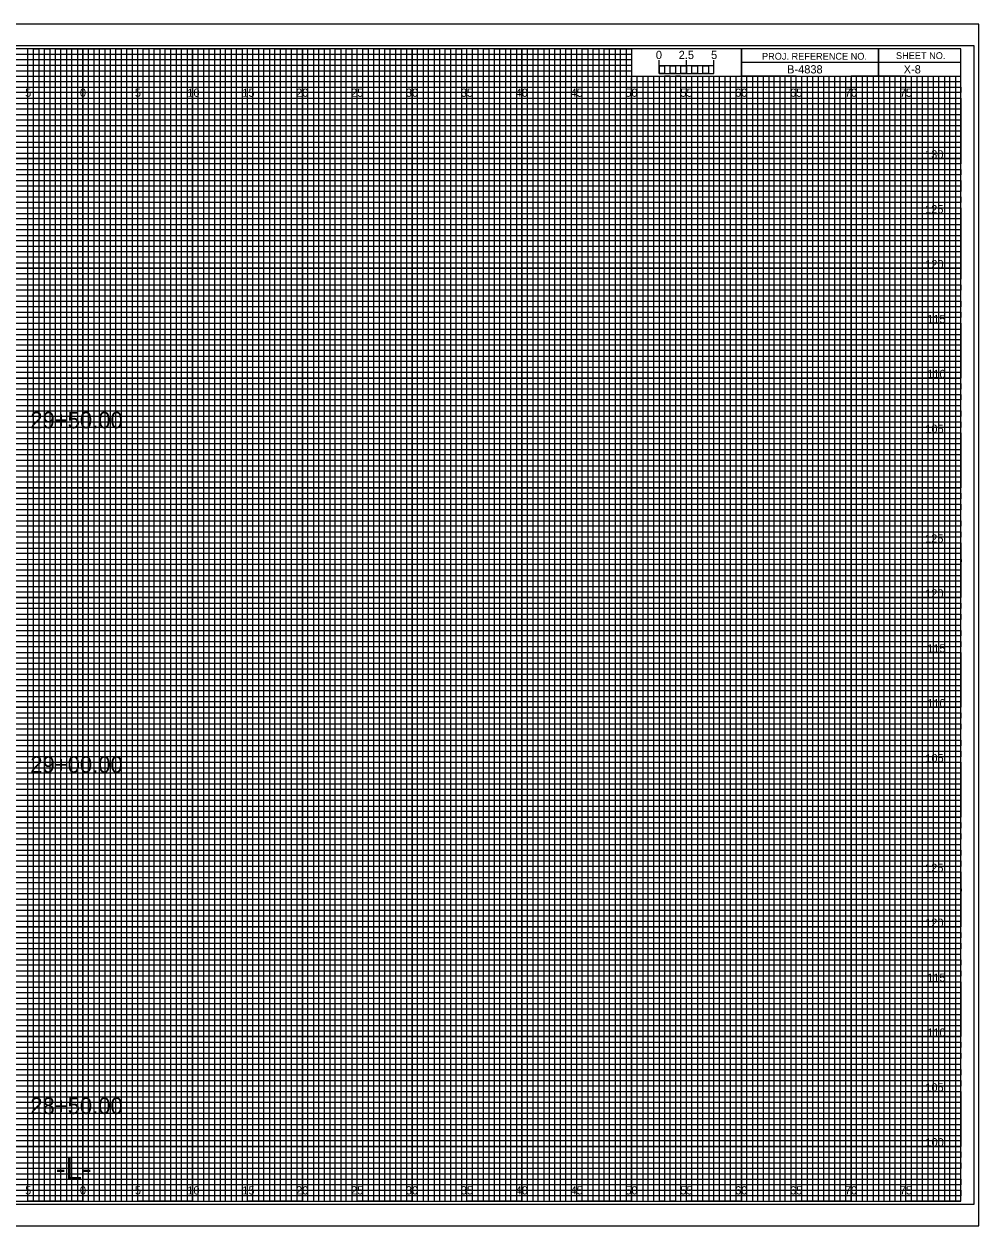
# Model space of a CAD drawing. Extents: x -7 to 182, y -2 to 1647.
# Drawn here: x 74.6 to 161.7, y 657.8 to 767.2 of the extents above; entities that cross this region are included whole.
import ezdxf

# ---------------------------------------------------------------- set-up
doc = ezdxf.new("R2010")
doc.units = 0
for name, color, linetype in [('Exist CMT Pavement', 7, 'Continuous'), ('Exist Cross Section Cell', 7, 'Continuous'), ('Exist XS Ground Line', 7, 'Continuous'), ('Prop CMT Pvmt Course 1', 7, 'Continuous'), ('Prop CMT Pvmt Course 2', 7, 'Continuous'), ('Prop CMT Pvmt Course 2 Wedge', 7, 'Continuous'), ('Prop CMT Pvmt Course 3', 7, 'Continuous'), ('Prop CMT Pvmt Surface', 7, 'Continuous'), ('Prop CMT Pvmt Surface Shoulder', 7, 'Continuous'), ('Prop CMT Pvmt Wedge Surface 1', 7, 'Continuous'), ('Prop CMT Pvmt Wedge Surface 2', 7, 'Continuous'), ('Prop CMT Pvmt Wedge Surface 3', 7, 'Continuous'), ('Prop CMT Shld Paved Course 1', 7, 'Continuous'), ('Prop CMT Shld Paved Course 2', 7, 'Continuous'), ('Prop CMT Shld Paved Course 3', 7, 'Continuous'), ('Prop CMT Slope Grass', 7, 'Continuous'), ('Prop CMT Subgrade Earthwork', 7, 'Continuous')]:
    doc.layers.add(name, color=color, linetype=linetype)

msp = doc.modelspace()

# ---------------------------------------------------------------- linework, layer by layer
at = {"layer": 'Exist XS Ground Line'}
for p, q in [((75, 765), (70, 765)), ((75, 660), (75, 765)), ((85, 765), (80, 765)), ((80, 765), (80, 660)), ((85, 660), (85, 765)), ((95, 765), (90, 765)), ((90, 765), (90, 660)), ((95, 660), (95, 765)), ((105, 765), (100, 765)), ((100, 765), (100, 660)), ((105, 660), (105, 765)), ((115, 765), (110, 765)), ((110, 765), (110, 660)), ((115, 660), (115, 765)), ((125, 765), (120, 765)), ((120, 765), (120, 660)), ((125, 660), (125, 765)), ((130, 765), (130, 660)), ((135, 660), (135, 762.5)), ((145, 762.5), (140, 762.5)), ((140, 762.5), (140, 660)), ((145, 660), (145, 762.5)), ((155, 762.5), (150, 762.5)), ((150, 762.5), (150, 660)), ((155, 660), (155, 762.5)), ((80, 660), (75, 660)), ((90, 660), (85, 660)), ((100, 660), (95, 660)), ((110, 660), (105, 660)), ((120, 660), (115, 660)), ((130, 660), (125, 660)), ((140, 660), (135, 660)), ((150, 660), (145, 660)), ((160, 660), (155, 660)), ((160, 660), (160, 660))]:
    msp.add_line(p, q, dxfattribs=at)
for points in [[(0, 760), (160, 760), (160, 755), (0, 755)], [(0, 750), (160, 750), (160, 745), (0, 745)], [(0, 740), (160, 740), (160, 735), (0, 735)], [(0, 730), (160, 730), (160, 725), (0, 725)], [(0, 720), (160, 720), (160, 715), (0, 715)], [(0, 710), (160, 710), (160, 705), (0, 705)], [(0, 700), (160, 700), (160, 695), (0, 695)], [(0, 690), (160, 690), (160, 685), (0, 685)], [(0, 680), (160, 680), (160, 675), (0, 675)], [(0, 670), (160, 670), (160, 665), (0, 665)]]:
    msp.add_lwpolyline(points, dxfattribs=at)
at = {"layer": 'Prop CMT Pvmt Course 2'}
for p, q in [((132.5, 762.75), (132.5, 763.95)), ((132.5, 763.45), (132.5, 763.95)), ((135, 762.75), (135, 763.95)), ((137.5, 762.75), (137.5, 763.95)), ((137.5, 763.45), (137.5, 763.95))]:
    msp.add_line(p, q, dxfattribs=at)
for points in [[(137.5, 763.45), (132.5, 763.45), (132.5, 762.75), (137.5, 762.75)], [(132.5, 763.45), (133, 763.45), (133, 762.75), (132.5, 762.75)], [(133.5, 763.45), (134, 763.45), (134, 762.75), (133.5, 762.75)], [(134.5, 763.45), (135, 763.45), (135, 762.75), (134.5, 762.75)], [(135.5, 763.45), (136, 763.45), (136, 762.75), (135.5, 762.75)], [(136.5, 763.45), (137, 763.45), (137, 762.75), (136.5, 762.75)]]:
    msp.add_lwpolyline(points, close=True, dxfattribs=at)
at = {"layer": 'Prop CMT Pvmt Course 3'}
msp.add_lwpolyline([(-6.7, 657.75), (161.65, 657.75), (161.65, 767.25), (-6.7, 767.25)], close=True, dxfattribs=at)
at = {"layer": 'Prop CMT Pvmt Wedge Surface 1'}
for p, q in [((0, 764.5), (130, 764.5)), ((130, 764.5), (130, 763.99)), ((130, 763.99), (0, 763.99)), ((0, 763.5), (130, 763.5)), ((130, 763.5), (130, 762.95)), ((130, 762.95), (0, 762.95)), ((0, 762), (160, 762))]:
    msp.add_line(p, q, dxfattribs=at)
for points in [[(0, 761.5), (135, 761.5), (160, 761.5), (160, 761), (0, 761)], [(0, 760.5), (160, 760.5), (160, 759.5), (0, 759.5)], [(0, 759), (160, 759), (160, 758.5), (0, 758.49)], [(0, 758), (160, 758), (160, 757), (0, 757)], [(0, 756.5), (160, 756.5), (160, 756), (0, 756)], [(0, 755.5), (160, 755.5), (160, 754.5), (0, 754.5)], [(0, 754), (160, 754), (160, 753.5), (0, 753.5)], [(0, 753), (160, 753), (160, 752), (0, 752)], [(0, 751.5), (160, 751.5), (160, 751), (0, 751)], [(0, 750.5), (160, 750.5), (160, 749.5), (0, 749.5)], [(0, 749), (160, 749), (160, 748.5), (0, 748.5)], [(0, 748), (160, 748), (160, 746.98), (160, 746.5), (160, 746), (0, 746)], [(0, 747), (160, 747), (160, 746.5), (0, 746.5)], [(0, 745.5), (160, 745.5), (160, 744.5), (0, 744.51)], [(0, 744.51), (160, 744.5), (160, 744), (0, 744)], [(0, 743.5), (160, 743.5), (160, 743), (0, 743)], [(0, 742), (160, 742), (160, 741.5), (0, 741.5)], [(0, 741), (160, 741), (160, 740.5), (0, 740.5)], [(-0.04, 739.45), (160, 739.45), (160, 738.94), (-0.04, 738.94)], [(0, 738.5), (160, 738.5), (160, 738), (0, 738)], [(0, 737), (160, 737), (160, 736.5), (0, 736.5)], [(0, 736), (160, 736), (160, 735.5), (0, 735.5)], [(0, 734.5), (160, 734.5), (160, 734), (0, 734)], [(0, 733.5), (160, 733.5), (160, 733), (0, 733)], [(0, 732), (160, 732), (160, 731.5), (0, 731.5)], [(0, 731), (160, 731), (160, 730.5), (0, 730.5)], [(0, 729.5), (160, 729.5), (160, 728.99), (0, 729)], [(0, 728.5), (160, 728.5), (160, 728), (0, 728)], [(0, 727), (160, 727), (160, 726.5), (0, 726.5)], [(0, 726), (160, 726), (160, 725.5), (0, 725.5)], [(0, 724.5), (160, 724.5), (160, 724), (0, 724)], [(0, 723.5), (160, 723.5), (160, 723), (0, 723)], [(0, 722), (160, 722), (160, 721.5), (0, 721.5)], [(0, 721), (160, 721), (160, 720.5), (0, 720.5)], [(0, 719.5), (160, 719.5), (160, 719), (0, 719)], [(0, 718.5), (160.03, 718.46), (160, 718), (0, 718)], [(0, 717), (160, 717), (160, 716.5), (0, 716.5)], [(0, 716), (160, 716), (160, 715.5), (0, 715.5)], [(0, 714.5), (160, 714.5), (160, 714), (0, 714)], [(0, 713.5), (160, 713.5), (160, 713), (0, 713)], [(0, 712), (160, 712), (160, 711.5), (0, 711.5)], [(0, 711), (160, 711), (160, 710.5), (0, 710.5)], [(0, 709.5), (160, 709.5), (160, 709), (0, 709)], [(0, 708.5), (160, 708.5), (160, 708), (0, 708)], [(0, 707), (160, 707), (160, 706.5), (0, 706.5)], [(0, 706), (160, 706), (160, 705.5), (0, 705.5)], [(0, 704.5), (160, 704.5), (160, 704), (0, 704)], [(0, 703.5), (160, 703.5), (160, 703), (0, 703)], [(0, 702), (160, 702), (160, 701.5), (0, 701.5)], [(0, 701), (160, 701), (160, 700.5), (0, 700.5)], [(0, 699.5), (160, 699.5), (160, 698.99), (0, 699)], [(0, 698.5), (160, 698.5), (160, 698), (0, 698)], [(0, 697), (160, 697), (160, 696.5), (0, 696.5)], [(0, 696), (160, 696), (160, 695.5), (0, 695.5)], [(0, 694.5), (160, 694.5), (160, 694), (0, 694)], [(0, 693.5), (160, 693.5), (160, 693), (0, 693)], [(0, 692), (160, 692), (160, 691.5), (0, 691.5)], [(0, 691), (160, 691), (160, 690.5), (0, 690.5)], [(0, 689.5), (160, 689.5), (160, 689), (0, 689)], [(0, 688.5), (160.03, 688.46), (160, 688), (0, 688)], [(0, 687), (160, 687), (160, 686.5), (0, 686.5)], [(0, 686), (160, 686), (160, 685.5), (0, 685.5)], [(0, 684.5), (160, 684.5), (160, 684), (0, 684)], [(0, 683.5), (160, 683.5), (160, 683), (0, 683)], [(0, 682), (160, 682), (160, 681.5), (0, 681.5)], [(0, 681), (160, 681), (160, 680.5), (0, 680.5)], [(0, 679.5), (160, 679.5), (160, 679), (0, 679)], [(0, 678.5), (160, 678.5), (160, 678), (0, 678)], [(0, 677), (160, 677), (160, 676.5), (0, 676.5)], [(0, 676), (160, 676), (160, 675.5), (0, 675.5)], [(0, 674.5), (160, 674.5), (160, 674), (0, 674)], [(0, 673.5), (160, 673.5), (160, 673), (0, 673)], [(0, 672), (160, 672), (160, 671.5), (0, 671.5)], [(0, 671), (160, 671), (160, 670.5), (0, 670.5)], [(0, 669.5), (160, 669.5), (160, 669), (0, 669)], [(0, 668.5), (160, 668.5), (160, 668), (0, 668)], [(0, 667), (160, 667), (160, 666.5), (0, 666.5)], [(0, 666), (160, 666), (160, 665.5), (0, 665.5)], [(0, 664.5), (160, 664.5), (160, 664), (0, 664)], [(0, 663.5), (160, 663.5), (160, 663), (0, 663)], [(0, 662), (160, 662), (160, 661.5), (0, 661.5)], [(0, 661), (160, 661), (160, 660.5), (0, 660.5)]]:
    msp.add_lwpolyline(points, dxfattribs=at)
at = {"layer": 'Prop CMT Pvmt Wedge Surface 2'}
for p, q in [((152.5, 765), (152.5, 762.5)), ((152.5, 762.5), (152.5, 765)), ((160, 763.75), (140, 763.75)), ((140, 763.75), (140, 762.5)), ((140, 762.5), (160, 762.5))]:
    msp.add_line(p, q, dxfattribs=at)
for points in [[(160, 765), (0, 765), (0, 660), (160, 660)], [(140, 765), (130, 765), (130, 762.51), (140, 762.51)], [(160, 765), (140, 765), (140, 762.5), (160, 762.5)]]:
    msp.add_lwpolyline(points, close=True, dxfattribs=at)
at = {"layer": 'Prop CMT Pvmt Wedge Surface 3'}
for p, q in [((133.5, 762.5), (133, 762.5)), ((133, 762.5), (133, 660)), ((133.5, 660), (133.5, 762.5)), ((134.5, 762.5), (134, 762.5)), ((134, 762.5), (134, 660)), ((134.5, 660), (134.5, 762.5)), ((133, 660), (132.5, 660)), ((134, 660), (133.5, 660))]:
    msp.add_line(p, q, dxfattribs=at)
for points in [[(75, 660), (75.5, 660), (75.5, 765), (76, 765), (76, 660)], [(76, 660), (76.5, 660), (76.5, 765), (77, 765), (77, 660)], [(77.5, 660), (78, 660), (78, 765), (78.5, 765), (78.5, 660)], [(78.5, 660), (79, 660), (79, 765), (79.5, 765), (79.5, 660)], [(80, 660), (80.5, 660), (80.5, 765), (81, 765), (81, 660)], [(81, 660), (81.5, 660), (81.5, 765), (82, 765), (82, 660)], [(82.5, 660), (83, 660), (83, 765), (83.5, 765), (83.5, 660)], [(83.5, 660), (84, 660), (84, 765), (84.5, 765), (84.5, 660)], [(85, 660), (85.5, 660), (85.5, 765), (86, 765), (86, 660)], [(86, 660), (86.5, 660), (86.5, 765), (87, 765), (87, 660)], [(87.5, 660), (88, 660), (88, 765), (88.5, 765), (88.5, 660)], [(88.5, 660), (89, 660), (89, 765), (89.5, 765), (89.5, 660)], [(90, 660), (90.5, 660), (90.5, 765), (91, 765), (91, 660)], [(91, 660), (91.5, 660), (91.5, 765), (92, 765), (92, 660)], [(92.5, 660), (93, 660), (93, 765), (93.5, 765), (93.5, 660)], [(93.5, 660), (94, 660), (94, 765), (94.5, 765), (94.5, 660)], [(95, 660), (95.5, 660), (95.5, 765), (96, 765), (96, 660)], [(96, 660), (96.5, 660), (96.5, 765), (97, 765), (97, 660)], [(97.5, 660), (98, 660), (98, 765), (98.5, 765), (98.5, 660)], [(98.5, 660), (99, 660), (99, 765), (99.5, 765), (99.5, 660)], [(100, 660), (100.5, 660), (100.5, 765), (101, 765), (101, 660)], [(101, 660), (101.5, 660), (101.5, 765), (102, 765), (102, 660)], [(102.5, 660), (103, 660), (103, 765), (103.5, 765), (103.5, 660)], [(103.5, 660), (104, 660), (104, 765), (104.5, 765), (104.5, 660)], [(105, 660), (105.5, 660), (105.5, 765), (106, 765), (106, 660)], [(106, 660), (106.5, 660), (106.5, 765), (107, 765), (107, 660)], [(107.5, 660), (108, 660), (108, 765), (108.5, 765), (108.5, 660)], [(108.5, 660), (109, 660), (109, 765), (109.5, 765), (109.5, 660)], [(110, 660), (110.5, 660), (110.5, 765), (111, 765), (111, 660)], [(111, 660), (111.5, 660), (111.5, 765), (112, 765), (112, 660)], [(112.5, 660), (113, 660), (113, 765), (113.5, 765), (113.5, 660)], [(113.5, 660), (114, 660), (114, 765), (114.5, 765), (114.5, 660)], [(115, 660), (115.5, 660), (115.5, 765), (116, 765), (116, 660)], [(116, 660), (116.5, 660), (116.5, 765), (117, 765), (117, 660)], [(117.5, 660), (118, 660), (118, 765), (118.5, 765), (118.5, 660)], [(118.5, 660), (119, 660), (119, 765), (119.5, 765), (119.5, 660)], [(120, 660), (120.5, 660), (120.5, 765), (121, 765), (121, 660)], [(121, 660), (121.5, 660), (121.5, 765), (122, 765), (122, 660)], [(122.5, 660), (123, 660), (123, 765), (123.5, 765), (123.5, 660)], [(123.5, 660), (124, 660), (124, 765), (124.5, 765), (124.5, 660)], [(125, 660), (125.5, 660), (125.5, 765), (126, 765), (126, 660)], [(126, 660), (126.5, 660), (126.5, 765), (127, 765), (127, 660)], [(127.5, 660), (128, 660), (128, 765), (128.5, 765), (128.5, 660)], [(128.5, 660), (129, 660), (129, 765), (129.5, 765), (129.5, 660)], [(130, 660), (130.5, 660), (130.5, 762.5), (131.01, 762.5), (131.01, 660)], [(131, 660), (131.5, 660), (131.5, 762.5), (132, 762.5), (132, 660)], [(135, 660), (135.49, 660), (135.49, 762.5), (136, 762.5), (136, 660)], [(136, 660), (136.5, 660), (136.5, 762.5), (137.03, 762.5), (137.03, 660)], [(137.5, 660), (138, 660), (138, 762.5), (138.5, 762.5), (138.5, 660)], [(138.5, 660), (139, 660), (139, 762.5), (139.5, 762.5), (139.5, 660)], [(140, 660), (140.5, 660), (140.5, 762.5), (141, 762.5), (141, 660)], [(141, 660), (141.5, 660), (141.5, 762.5), (142, 762.5), (142, 660)], [(142.5, 660), (143, 660), (143, 762.5), (143.5, 762.5), (143.5, 660)], [(143.5, 660), (144, 660), (144, 762.5), (144.5, 762.5), (144.5, 660)], [(145, 660), (145.5, 660), (145.5, 762.5), (146, 762.5), (146, 660)], [(146, 660), (146.5, 660), (146.5, 762.5), (147, 762.5), (147, 660)], [(147.5, 660), (148, 660), (148, 762.5), (148.5, 762.5), (148.5, 660)], [(148.5, 660), (149, 660), (149, 762.5), (149.5, 762.5), (149.5, 660)], [(150, 660), (150.5, 660), (150.5, 762.5), (151, 762.5), (151, 660)], [(151, 660), (151.5, 660), (151.5, 762.5), (152, 762.5), (152, 660)], [(152.5, 660), (153, 660), (153, 762.5), (153.5, 762.5), (153.5, 660)], [(153.5, 660), (154, 660), (154, 762.5), (154.5, 762.5), (154.5, 660)], [(155, 660), (155.5, 660), (155.5, 762.5), (156, 762.5), (156, 660)], [(156, 660), (156.5, 660), (156.5, 762.5), (157, 762.5), (157, 660)], [(157.5, 660), (158, 660), (158, 762.5), (158.5, 762.5), (158.5, 660)], [(158.5, 660), (159, 660), (159, 762.5), (159.5, 762.5), (159.5, 660)]]:
    msp.add_lwpolyline(points, dxfattribs=at)
at = {"layer": 'Prop CMT Shld Paved Course 1'}
for p, q in [((75, 660), (75, 765)), ((80, 660), (80, 765)), ((85, 660), (85, 765)), ((90, 660), (90, 765)), ((95, 660), (95, 765)), ((100, 660), (100, 765)), ((105, 660), (105, 765)), ((110, 660), (110, 765)), ((115, 660), (115, 765)), ((120, 660), (120, 765)), ((125, 660), (125, 765)), ((130, 660), (130, 762.34)), ((135, 660), (135, 762.34)), ((140, 660), (140, 762.34)), ((145, 660), (145, 762.34)), ((150, 660), (150, 762.34)), ((155, 660), (155, 762.34)), ((0, 760), (160, 760)), ((0, 755), (160, 755)), ((0, 750), (160, 750)), ((0, 745), (160, 745)), ((0, 740), (160, 740)), ((0, 735), (160, 735)), ((0, 730), (160, 730)), ((0, 725), (160, 725)), ((0, 720), (160, 720)), ((0, 715), (160, 715)), ((0, 710), (160, 710)), ((0, 705), (160, 705)), ((0, 700), (160, 700)), ((0, 695), (160, 695)), ((0, 690), (160, 690)), ((0, 685), (160, 685)), ((0, 680), (160, 680)), ((0, 675), (160, 675)), ((0, 670), (160, 670)), ((0, 665), (160, 665))]:
    msp.add_line(p, q, dxfattribs=at)
at = {"layer": 'Prop CMT Shld Paved Course 2'}
for p, q in [((161.65, 767.25), (-6.7, 767.25)), ((-6.7, 657.75), (161.65, 657.75))]:
    msp.add_line(p, q, dxfattribs=at)
at = {"layer": 'Prop CMT Slope Grass'}
msp.add_lwpolyline([(-5.4, 659.75), (161.2, 659.75), (161.2, 765.25), (-5.4, 765.25)], close=True, dxfattribs=at)
at = {"layer": 'Prop CMT Subgrade Earthwork'}
for points in [[(72.5, 660), (77.5, 660), (77.5, 765), (82.5, 765), (82.5, 660), (87.5, 660), (87.5, 765), (92.5, 765), (92.5, 660), (97.5, 660), (97.5, 765), (102.5, 765), (102.5, 660), (107.5, 660), (107.5, 765), (112.5, 765), (112.5, 660), (117.5, 660), (117.5, 765), (122.5, 765), (122.5, 660), (127.5, 660), (127.5, 765), (129.97, 765), (130, 765), (130, 762.5), (132.5, 762.5), (132.5, 660), (137.5, 660), (137.5, 762.5), (142.5, 762.5), (142.5, 660), (147.5, 660), (147.5, 762.5), (152.5, 762.5), (152.5, 660), (157.5, 660), (157.5, 762.5)], [(0, 762.5), (137.5, 762.5)], [(0, 752.5), (160, 752.5), (160, 757.5), (0, 757.5)], [(0, 742.5), (160, 742.5), (160, 747.5), (0, 747.5)], [(0, 732.5), (160, 732.5), (160, 737.5), (0, 737.5)], [(0, 722.5), (160, 722.5), (160, 727.5), (0, 727.5)], [(0, 712.5), (160, 712.5), (160, 717.5), (0, 717.5)], [(0, 702.5), (160, 702.5), (160, 707.5), (0, 707.5)], [(0, 692.5), (160, 692.5), (160, 697.5), (0, 697.5)], [(0, 682.5), (160, 682.5), (160, 687.5), (0, 687.5)], [(0, 672.5), (160, 672.5), (160, 677.5), (0, 677.5)], [(0, 662.5), (160, 662.5), (160, 667.5), (0, 667.5)]]:
    msp.add_lwpolyline(points, dxfattribs=at)

# ---------------------------------------------------------------- texts
at = {"layer": 'Exist CMT Pavement'}
for s, p in [('29+50.00', (75.21, 730.42)), ('29+00.00', (75.21, 699.04)), ('28+50.00', (75.21, 667.95))]:
    msp.add_text(s, height=1.5, dxfattribs=at).set_placement(p)
at = {"layer": 'Exist Cross Section Cell'}
for s, p in [('5', (74.74, 760.62)), ('0', (79.73, 760.62)), ('0', (79.73, 760.62)), ('5', (84.74, 760.62)), ('10', (89.52, 760.62)), ('15', (94.53, 760.62)), ('20', (99.43, 760.62)), ('25', (104.44, 760.62)), ('30', (109.43, 760.62)), ('35', (114.44, 760.62)), ('40', (119.43, 760.62)), ('45', (124.44, 760.62)), ('50', (129.43, 760.62)), ('55', (134.44, 760.62)), ('60', (139.43, 760.62)), ('65', (144.44, 760.62)), ('70', (149.43, 760.62)), ('75', (154.44, 760.62)), ('0', (79.73, 660.62)), ('0', (79.73, 660.62)), ('10', (89.52, 660.62)), ('20', (99.43, 660.62)), ('25', (104.44, 660.62)), ('30', (109.43, 660.62)), ('35', (114.44, 660.62)), ('40', (119.43, 660.62)), ('50', (129.43, 660.62)), ('60', (139.43, 660.62)), ('65', (144.44, 660.62)), ('70', (149.43, 660.62)), ('5', (74.74, 660.62)), ('5', (84.74, 660.62)), ('15', (94.53, 660.62)), ('45', (124.44, 660.62)), ('55', (134.44, 660.62)), ('75', (154.44, 660.62))]:
    msp.add_text(s, height=0.75, dxfattribs=at).set_placement(p)
at = {"layer": 'Prop CMT Pvmt Course 1'}
msp.add_text('-L-', height=2, dxfattribs=at).set_placement((77.53, 662))
at = {"layer": 'Prop CMT Pvmt Course 2'}
msp.add_text('0', height=0.75, dxfattribs=at).set_placement((132.21, 764.06))
at = {"layer": 'Prop CMT Pvmt Course 2 Wedge'}
for s, p in [('2.5', (134.29, 764.06)), ('5', (137.24, 764.06))]:
    msp.add_text(s, height=0.75, dxfattribs=at).set_placement(p)
at = {"layer": 'Prop CMT Pvmt Surface'}
msp.add_text('X-8', height=0.75, dxfattribs=at).set_placement((154.79, 762.75))
at = {"layer": 'Prop CMT Pvmt Surface Shoulder'}
msp.add_text('B-4838', height=0.75, dxfattribs=at).set_placement((144.17, 762.75))
at = {"layer": 'Prop CMT Pvmt Wedge Surface 2'}
for s, p in [('PROJ. REFERENCE NO.', (141.88, 764)), ('SHEET NO.', (154.09, 764.06))]:
    msp.add_text(s, height=0.625, dxfattribs=at).set_placement(p)
at = {"layer": 'Prop CMT Shld Paved Course 3'}
for s, p in [('130', (156.74, 755)), ('125', (156.74, 750)), ('120', (156.75, 745)), ('115', (156.93, 740)), ('110', (156.94, 735)), ('105', (156.76, 730)), ('125', (156.74, 720)), ('120', (156.75, 715)), ('115', (156.93, 710)), ('110', (156.94, 705)), ('105', (156.76, 700)), ('125', (156.74, 690)), ('120', (156.75, 685)), ('115', (156.93, 680)), ('110', (156.94, 675)), ('105', (156.76, 670)), ('100', (156.77, 665))]:
    msp.add_text(s, height=0.75, dxfattribs=at).set_placement(p)

doc.saveas('drawing.dxf')
